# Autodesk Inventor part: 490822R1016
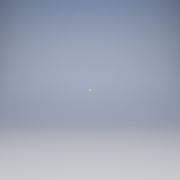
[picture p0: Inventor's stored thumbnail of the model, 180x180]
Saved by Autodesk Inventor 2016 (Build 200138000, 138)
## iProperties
Created: 2019-08
Part Number: 490822R1016
Material: 일반
Document SubType Name: Modeling
Designer: EDU-1-15
Density: 1 g/cm^3
Appearance: 기본값
Author: EDU-1-15
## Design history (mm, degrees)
sketch "스케치1"
  geometry: 1 further point
  constraints: 1 other
